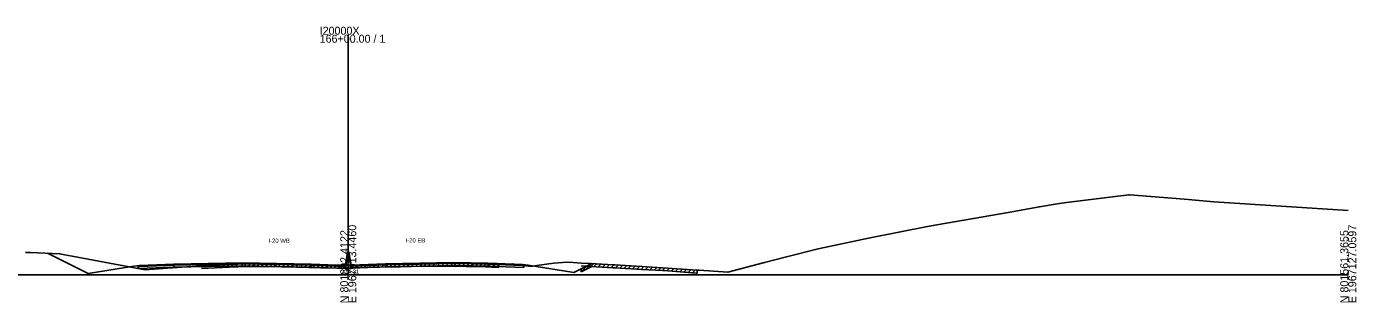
# Model space of a CAD drawing. Extents: x -4026 to 9638, y -10 to 19609.
# Drawn here: x 4237.4 to 4702.8, y 7490.3 to 7586.8 of the extents above; entities that cross this region are included whole.
import ezdxf

# ---------------------------------------------------------------- set-up
doc = ezdxf.new("R2010")
doc.units = 0
for name, color, linetype in [('RD_GPK_XS_Cell', 7, 'Continuous'), ('RD_TX_Misc1', 7, 'Continuous'), ('RD_XS_Base', 7, 'Continuous'), ('RD_XS_ExGround', 7, 'Continuous'), ('RD_XS_ExPaveRet', 7, 'Continuous'), ('RD_XS_Greenside', 7, 'Continuous'), ('RD_XS_MedBWall', 7, 'Continuous'), ('RD_XS_Pave', 7, 'Continuous'), ('RD_XS_PaveOvlay', 7, 'Continuous'), ('RD_XS_TieSlope', 7, 'Continuous'), ('RD_XS_TX_Elev_EX', 7, 'Continuous')]:
    doc.layers.add(name, color=color, linetype=linetype)

msp = doc.modelspace()

# ---------------------------------------------------------------- linework, layer by layer
at = {"layer": 'RD_GPK_XS_Cell'}
for p, q in [((4350, 7500), (4350, 7583.96)), ((4000, 7500), (4350, 7500)), ((4350, 7500), (4700, 7500))]:
    msp.add_line(p, q, dxfattribs=at)
at = {"layer": 'RD_XS_Base'}
for points in [[(4276.5, 7502.84), (4277, 7502.86), (4289, 7503.33)], [(4276.5, 7502.17), (4276.5, 7502.84)], [(4289, 7502.66), (4276.5, 7502.17)], [(4337, 7503.33), (4313, 7503.82), (4289, 7503.33)], [(4289, 7503.33), (4289, 7502.66)], [(4289, 7503.33), (4289, 7503.33), (4289, 7502.66), (4289, 7502.66)], [(4289, 7502.66), (4313, 7503.15), (4337, 7502.66)], [(4337, 7502.66), (4337, 7503.33)], [(4349, 7502.86), (4337, 7503.33)], [(4337, 7502.66), (4349, 7502.19)], [(4349, 7502.19), (4349, 7502.86)], [(4351, 7502.98), (4363, 7503.46)], [(4351, 7502.31), (4351, 7502.98)], [(4363, 7502.79), (4351, 7502.31)], [(4363, 7503.46), (4387, 7503.94), (4399, 7503.7)], [(4363, 7502.79), (4363, 7503.46)], [(4399, 7503.03), (4387, 7503.27), (4363, 7502.79)], [(4399, 7503.7), (4399, 7503.7), (4399, 7503.03), (4399, 7503.03)], [(4399, 7503.03), (4399, 7503.7)], [(4411.5, 7503.2), (4411, 7503.22), (4399, 7503.7)], [(4399, 7503.03), (4411.5, 7502.53)], [(4411.5, 7502.53), (4411.5, 7503.2)]]:
    msp.add_lwpolyline(points, dxfattribs=at)
at = {"layer": 'RD_XS_ExGround'}
msp.add_lwpolyline([(4236.99, 7507.82), (4238.85, 7507.72), (4248.98, 7507.35), (4258.98, 7505.47), (4278.98, 7501.71), (4288.41, 7502.38), (4298.62, 7503.15), (4303.44, 7503.39), (4308.49, 7503.65), (4311.39, 7503.71), (4320.64, 7503.9), (4326.4, 7503.74), (4332.01, 7503.58), (4340.28, 7503.43), (4342.99, 7503.38), (4346.73, 7503.32), (4349.02, 7503.28), (4350, 7503.31), (4351.79, 7503.38), (4358.16, 7503.6), (4361.07, 7503.64), (4368.21, 7503.77), (4376.27, 7503.96), (4379.89, 7504.04), (4391.24, 7503.92), (4392.16, 7503.91), (4392.79, 7503.89), (4398.03, 7503.77), (4400.29, 7503.65), (4402.72, 7503.56), (4406.32, 7503.71), (4407.59, 7503.75), (4407.97, 7503.66), (4413.87, 7502.89), (4415.96, 7503.18), (4422.01, 7503.99), (4424.95, 7504.21), (4426.4, 7504.44), (4428.75, 7504.25), (4431.5, 7504.05), (4434.75, 7503.89), (4442.76, 7503.43), (4443.35, 7503.4), (4452.7, 7502.86), (4460, 7502.42), (4461.81, 7502.31), (4463.41, 7502.19), (4470.32, 7501.69), (4471.75, 7501.59), (4472.11, 7501.57), (4472.79, 7501.53), (4482.81, 7500.94), (4495.67, 7504.22), (4503.42, 7506.23), (4514.46, 7509), (4532.14, 7512.77), (4553.28, 7516.95), (4580.92, 7521.77), (4591.89, 7523.78), (4598.08, 7524.8), (4601.37, 7525.31), (4623.2, 7527.95), (4623.58, 7527.99), (4642.65, 7526.44), (4652.89, 7525.51), (4698.21, 7522.62), (4700, 7522.44)], dxfattribs=at)
at = {"layer": 'RD_XS_ExPaveRet'}
for p, q in [((4298.62, 7502.86), (4298.92, 7503.16)), ((4298.62, 7502.86), (4313, 7503.15)), ((4298.62, 7502.86), (4298.62, 7503.15)), ((4300.12, 7502.89), (4300.47, 7503.24)), ((4301.62, 7502.92), (4302.02, 7503.32)), ((4303.12, 7502.95), (4303.57, 7503.4)), ((4303.44, 7502.39), (4308.49, 7502.65)), ((4304.62, 7502.98), (4305.12, 7503.48)), ((4306.12, 7503.01), (4306.67, 7503.56)), ((4307.62, 7503.04), (4308.22, 7503.64)), ((4308.49, 7502.65), (4311.39, 7502.71)), ((4309.12, 7503.07), (4309.73, 7503.68)), ((4310.62, 7503.1), (4311.23, 7503.71)), ((4311.39, 7502.71), (4320.64, 7502.9)), ((4312.12, 7502.72), (4313.14, 7503.74)), ((4313, 7503.15), (4337, 7502.67)), ((4313.62, 7503.14), (4314.25, 7503.77)), ((4315.12, 7503.11), (4315.81, 7503.8)), ((4316.62, 7503.08), (4317.38, 7503.83)), ((4318.12, 7503.05), (4318.94, 7503.86)), ((4319.62, 7503.02), (4320.5, 7503.89)), ((4320.64, 7502.9), (4326.4, 7502.74)), ((4321.12, 7502.99), (4322, 7503.86)), ((4322.62, 7502.96), (4323.49, 7503.82)), ((4324.12, 7502.93), (4324.98, 7503.78)), ((4325.62, 7502.9), (4326.46, 7503.74)), ((4326.4, 7502.74), (4332.01, 7502.58)), ((4327.12, 7502.87), (4327.95, 7503.7)), ((4328.62, 7502.84), (4329.44, 7503.66)), ((4330.12, 7502.81), (4330.93, 7503.61)), ((4331.62, 7502.78), (4332.42, 7503.58)), ((4332.01, 7502.58), (4340.28, 7502.43)), ((4333.12, 7502.56), (4334.1, 7503.54)), ((4334.62, 7502.53), (4335.6, 7503.52)), ((4336.12, 7502.51), (4337.1, 7503.49)), ((4337, 7502.67), (4349, 7502.19)), ((4337.62, 7502.65), (4338.44, 7503.46)), ((4339.12, 7502.59), (4339.97, 7503.43)), ((4340.28, 7502.43), (4342.99, 7502.38)), ((4340.62, 7502.53), (4341.51, 7503.41)), ((4342.12, 7502.47), (4343.04, 7503.38)), ((4343.62, 7502.41), (4344.57, 7503.35)), ((4345.12, 7502.35), (4346.08, 7503.31)), ((4346.62, 7502.29), (4347.58, 7503.25)), ((4348.12, 7502.29), (4349.11, 7503.28)), ((4349, 7502.19), (4349.75, 7506.98)), ((4349.62, 7502.3), (4350.66, 7503.33)), ((4349.75, 7506.98), (4350.25, 7506.98)), ((4350.25, 7506.98), (4351, 7502.31)), ((4351, 7502.31), (4363, 7502.79)), ((4351.12, 7502.32), (4352.16, 7503.36)), ((4351.79, 7502.38), (4358.16, 7502.6)), ((4352.62, 7502.38), (4353.66, 7503.42)), ((4354.12, 7502.44), (4355.16, 7503.48)), ((4355.62, 7502.5), (4356.66, 7503.54)), ((4357.12, 7502.56), (4358.16, 7503.6)), ((4358.16, 7502.6), (4361.07, 7502.64)), ((4358.62, 7502.62), (4359.63, 7503.62)), ((4360.12, 7502.68), (4361.09, 7503.64)), ((4361.07, 7502.64), (4368.21, 7502.77)), ((4361.62, 7502.65), (4362.64, 7503.67)), ((4363, 7502.79), (4387, 7503.27)), ((4363.12, 7502.8), (4364.02, 7503.7)), ((4364.62, 7502.83), (4365.52, 7503.72)), ((4366.12, 7502.86), (4367.01, 7503.75)), ((4367.62, 7502.89), (4368.51, 7503.77)), ((4368.21, 7502.77), (4376.27, 7502.96)), ((4369.12, 7502.92), (4370.02, 7503.81)), ((4370.62, 7502.95), (4371.52, 7503.85)), ((4372.12, 7502.98), (4373.03, 7503.88)), ((4373.62, 7503.01), (4374.54, 7503.92)), ((4375.12, 7503.04), (4376.04, 7503.95)), ((4376.27, 7502.96), (4379.89, 7503.04)), ((4376.62, 7503.07), (4377.55, 7503.99)), ((4378.12, 7503.1), (4379.05, 7504.03)), ((4379.62, 7503.13), (4380.54, 7504.04)), ((4379.89, 7503.04), (4391.24, 7502.92)), ((4381.12, 7503.03), (4382.11, 7504.02)), ((4382.62, 7503.01), (4383.61, 7504)), ((4384.12, 7503), (4385.11, 7503.99)), ((4385.62, 7502.98), (4386.61, 7503.97)), ((4387, 7503.27), (4399, 7503.03)), ((4387.12, 7503.27), (4387.81, 7503.96)), ((4388.62, 7503.24), (4389.32, 7503.94)), ((4390.12, 7503.21), (4390.84, 7503.92)), ((4391.24, 7502.92), (4392.16, 7502.91)), ((4391.62, 7503.18), (4392.35, 7503.91)), ((4392.16, 7502.91), (4392.79, 7502.89)), ((4392.79, 7502.89), (4398.03, 7502.77)), ((4393.12, 7503.15), (4393.84, 7503.87)), ((4394.62, 7503.12), (4395.34, 7503.83)), ((4396.12, 7503.09), (4396.83, 7503.8)), ((4397.62, 7503.06), (4398.32, 7503.76)), ((4398.03, 7502.77), (4400.29, 7502.65)), ((4399, 7503.03), (4402.72, 7502.88)), ((4399.12, 7503.03), (4399.77, 7503.67)), ((4400.29, 7502.65), (4402.72, 7502.56)), ((4400.62, 7502.97), (4401.27, 7503.61)), ((4402.72, 7503.88), (4402.72, 7502.88)), ((4431.5, 7503.05), (4434.75, 7502.89)), ((4431.5, 7500.97), (4433.5, 7502.97)), ((4431.5, 7500.97), (4435.28, 7502.86)), ((4433, 7501.72), (4435, 7503.72)), ((4434.5, 7502.47), (4435.86, 7503.82)), ((4434.75, 7502.89), (4442.76, 7502.43)), ((4436, 7502.82), (4436.95, 7503.76)), ((4437.5, 7502.73), (4438.45, 7503.68)), ((4439, 7502.65), (4439.95, 7503.59)), ((4440.5, 7502.56), (4441.45, 7503.51)), ((4442, 7502.48), (4442.95, 7503.42)), ((4442.76, 7502.43), (4443.35, 7502.4)), ((4443.5, 7502.39), (4444.45, 7503.33)), ((4445, 7502.3), (4445.95, 7503.25)), ((4446.5, 7502.22), (4447.45, 7503.16)), ((4448, 7502.13), (4448.95, 7503.07)), ((4449.5, 7502.04), (4450.45, 7502.99)), ((4451, 7501.96), (4451.95, 7502.9)), ((4452.5, 7501.87), (4453.45, 7502.81)), ((4454, 7501.78), (4454.95, 7502.72)), ((4455.5, 7501.69), (4456.45, 7502.63)), ((4457, 7501.6), (4457.95, 7502.54)), ((4458.5, 7501.51), (4459.45, 7502.45)), ((4298.62, 7502.15), (4303.44, 7502.39)), ((4342.99, 7502.38), (4346.73, 7502.32)), ((4346.73, 7502.32), (4349.02, 7502.28)), ((4349.02, 7502.28), (4350, 7502.31)), ((4350, 7502.31), (4351.79, 7502.38)), ((4431.5, 7500.97), (4431.5, 7501.97)), ((4443.35, 7502.4), (4452.7, 7501.86)), ((4452.7, 7501.86), (4460, 7501.42)), ((4460, 7501.42), (4460.94, 7502.36)), ((4460, 7501.42), (4461.81, 7501.31)), ((4461.5, 7501.33), (4462.44, 7502.26)), ((4461.81, 7501.31), (4463.41, 7501.19)), ((4463, 7501.22), (4463.94, 7502.16)), ((4463.41, 7501.19), (4470.32, 7500.69)), ((4464.5, 7501.12), (4465.43, 7502.05)), ((4466, 7501.01), (4466.93, 7501.94)), ((4467.5, 7500.9), (4468.43, 7501.83)), ((4469, 7500.79), (4469.93, 7501.72)), ((4470.32, 7500.69), (4471.75, 7500.59)), ((4470.5, 7500.68), (4471.43, 7501.61)), ((4471.75, 7500.59), (4472.11, 7500.57)), ((4472.11, 7501.57), (4472.11, 7500.57))]:
    msp.add_line(p, q, dxfattribs=at)
at = {"layer": 'RD_XS_Greenside'}
for points in [[(4275, 7503.03), (4259, 7500.36)], [(4277, 7503.19), (4275, 7503.03)], [(4411, 7503.55), (4413, 7503.39)], [(4413, 7503.39), (4429, 7500.72)]]:
    msp.add_lwpolyline(points, dxfattribs=at)
at = {"layer": 'RD_XS_MedBWall'}
for points in [[(4349, 7503.19), (4349.75, 7507.98), (4350.25, 7507.98), (4351, 7503.31)], [(4349, 7502.19), (4349, 7503.19)], [(4351, 7503.31), (4351, 7502.19)], [(4351, 7502.19), (4349, 7502.19)]]:
    msp.add_lwpolyline(points, dxfattribs=at)
at = {"layer": 'RD_XS_Pave'}
for points in [[(4277, 7503.02), (4289, 7503.5)], [(4289, 7503.33), (4277, 7502.86)], [(4277, 7502.86), (4277, 7503.02)], [(4289, 7503.5), (4313, 7503.98), (4337, 7503.5)], [(4337, 7503.33), (4313, 7503.82), (4289, 7503.33)], [(4289, 7503.5), (4289, 7503.5), (4289, 7503.33), (4289, 7503.33)], [(4289, 7503.33), (4289, 7503.5)], [(4337, 7503.5), (4349, 7503.03)], [(4337, 7503.33), (4337, 7503.5)], [(4349, 7502.86), (4337, 7503.33)], [(4349, 7503.03), (4349, 7502.86)], [(4363, 7503.63), (4351, 7503.15)], [(4351, 7502.98), (4363, 7503.46)], [(4351, 7503.15), (4351, 7502.98)], [(4399, 7503.87), (4387, 7504.11), (4363, 7503.63)], [(4363, 7503.46), (4387, 7503.94), (4399, 7503.7)], [(4363, 7503.63), (4363, 7503.46)], [(4399, 7503.87), (4399, 7503.87), (4399, 7503.7), (4399, 7503.7)], [(4399, 7503.7), (4399, 7503.87)], [(4411, 7503.39), (4399, 7503.87)], [(4399, 7503.7), (4411, 7503.22)], [(4411, 7503.22), (4411, 7503.39)]]:
    msp.add_lwpolyline(points, dxfattribs=at)
at = {"layer": 'RD_XS_PaveOvlay'}
for points in [[(4277, 7503.19), (4289, 7503.67)], [(4289, 7503.5), (4277, 7503.02)], [(4277, 7503.02), (4277, 7503.19)], [(4289, 7503.67), (4313, 7504.15), (4337, 7503.67)], [(4337, 7503.5), (4313, 7503.98), (4289, 7503.5)], [(4289, 7503.67), (4289, 7503.5)], [(4289, 7503.67), (4289, 7503.67), (4289, 7503.5), (4289, 7503.5)], [(4337, 7503.67), (4337, 7503.5)], [(4337, 7503.67), (4349, 7503.19)], [(4349, 7503.03), (4337, 7503.5)], [(4349, 7503.19), (4349, 7503.03)], [(4363, 7503.79), (4351, 7503.31)], [(4351, 7503.15), (4363, 7503.63)], [(4351, 7503.31), (4351, 7503.15)], [(4399, 7504.03), (4387, 7504.27), (4363, 7503.79)], [(4363, 7503.63), (4387, 7504.11), (4399, 7503.87)], [(4363, 7503.79), (4363, 7503.63)], [(4399, 7503.87), (4399, 7504.03)], [(4399, 7504.03), (4399, 7504.03), (4399, 7503.87), (4399, 7503.87)], [(4399, 7504.03), (4411, 7503.55)], [(4411, 7503.39), (4399, 7503.87)], [(4411, 7503.55), (4411, 7503.39)]]:
    msp.add_lwpolyline(points, dxfattribs=at)
at = {"layer": 'RD_XS_TieSlope'}
for points in [[(4259, 7500.36), (4244.72, 7507.5)], [(4429, 7500.72), (4435.28, 7503.86)]]:
    msp.add_lwpolyline(points, dxfattribs=at)

# ---------------------------------------------------------------- texts
at = {"layer": 'RD_GPK_XS_Cell'}
for s, p in [('I20000X', (4340, 7583.96)), ('166+00.00 / 1', (4340, 7581.16))]:
    msp.add_text(s, height=2.8, dxfattribs=at).set_placement(p)
for s, p in [('E 1967013.4460', (4352.8, 7490)), ('E 1967127.0597', (4702.8, 7490)), ('N 801892.4122', (4350, 7490)), ('N 801561.3655', (4700, 7490))]:
    msp.add_text(s, height=2.8, rotation=90, dxfattribs=at).set_placement(p)
at = {"layer": 'RD_TX_Misc1'}
for s, p in [('I-20 WB', (4322.06, 7511.15)), ('I-20 EB', (4370.06, 7511.27))]:
    msp.add_text(s, height=1.5, dxfattribs=at).set_placement(p)
at = {"layer": 'RD_XS_TX_Elev_EX'}
msp.add_text('274.31', height=1.5, dxfattribs=at).set_placement((4347.52, 7500.31))

doc.saveas('drawing.dxf')
